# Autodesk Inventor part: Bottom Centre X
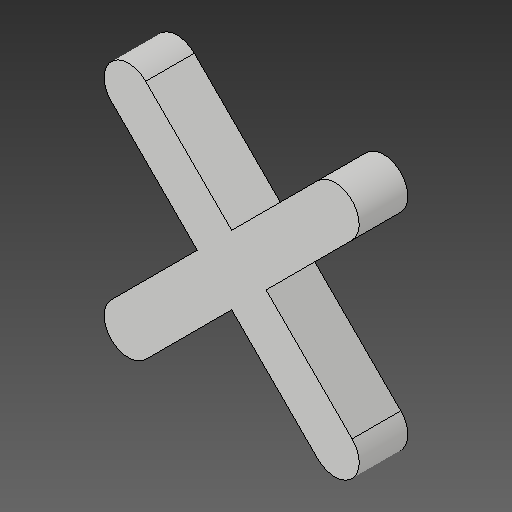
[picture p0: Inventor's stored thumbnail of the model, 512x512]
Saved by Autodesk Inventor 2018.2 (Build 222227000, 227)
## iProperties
Created: 2018-03
Part Number: Bottom Centre X
Material: Generic
Document SubType Name: Modeling
Designer: PeterMaxwell-Stewart
Mass: 1.57135 g
Surface Area: 12.8562 cm^2
Volume: 1.57135 cm^3
Density: 1 g/cm^3
Appearance: Default
Author: PeterMaxwell-Stewart
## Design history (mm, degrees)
derived "O's and X's.ipt"
feature "Bottom Centre X::O's and X's.ipt" dims "d0" = 10
tag "TaggingFeature1"
body "Solid1"
